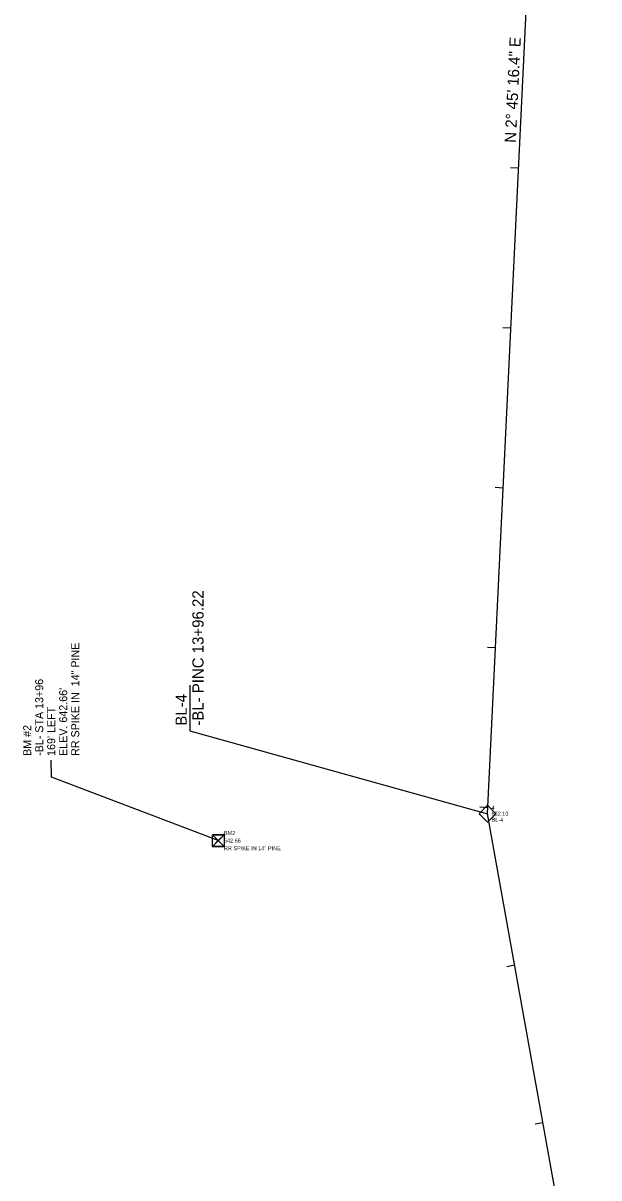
# Model space of a CAD drawing. Extents: x 1373003 to 1373999, y 549956 to 552815.
# Drawn here: x 1373404 to 1373764, y 551431 to 552153 of the extents above; entities that cross this region are included whole.
import ezdxf

# ---------------------------------------------------------------- set-up
doc = ezdxf.new("R2010")
doc.units = 0
for name, color, linetype in [('CTL Bench Mark CELL', 7, 'Continuous'), ('CTL Bench Mark Cogo Comment', 7, 'Continuous'), ('CTL Bench Mark Cogo Elevation', 7, 'Continuous'), ('CTL Bench Mark Cogo Number', 7, 'Continuous'), ('CTL Bench Mark Leader', 7, 'Continuous'), ('CTL Bench Mark Text', 7, 'Continuous'), ('CTL GPS Vertical CELL', 7, 'Continuous'), ('CTL Supplemental Horizontal and Vertical CELL', 7, 'Continuous'), ('CTL Supplemental Horizontal and Vertical Cogo Comment', 7, 'Continuous'), ('CTL Supplemental Horizontal and Vertical Cogo Elevation', 7, 'Continuous'), ('CTL Supplemental Horizontal and Vertical Cogo Number', 7, 'Continuous'), ('Exist Horizontal Baseline Alignment', 7, 'Continuous'), ('Exist Horizontal Baseline Alignment Direction Label', 7, 'Continuous'), ('Exist Horizontal Baseline Alignment Station Label', 7, 'Continuous'), ('Exist Horizontal Baseline Alignment Tick small', 7, 'Continuous')]:
    doc.layers.add(name, color=color, linetype=linetype)

msp = doc.modelspace()

# ---------------------------------------------------------------- linework, layer by layer
at = {"layer": 'CTL Bench Mark CELL'}
msp.add_line((1373526.28, 551641.82), (1373526.28, 551641.82), dxfattribs=at)
msp.add_lwpolyline([(1373522.68, 551645.41), (1373529.86, 551645.41), (1373529.86, 551638.22), (1373522.68, 551638.22)], close=True, dxfattribs=at)
for points in [[(1373529.86, 551645.41), (1373522.68, 551638.22), (1373526.27, 551641.81), (1373529.86, 551638.22), (1373522.68, 551645.41)], [(1373526.27, 551641.81), (1373529.86, 551645.41), (1373522.68, 551645.41), (1373526.27, 551641.81)], [(1373526.27, 551641.81), (1373522.68, 551638.22), (1373529.86, 551638.22), (1373526.27, 551641.81)]]:
    msp.add_lwpolyline(points, dxfattribs=at)
at = {"layer": 'CTL Bench Mark Leader'}
msp.add_lwpolyline([(1373526.28, 551641.82), (1373421.92, 551681.51), (1373421.87, 551692.16)], dxfattribs=at)
at = {"layer": 'CTL GPS Vertical CELL'}
msp.add_lwpolyline([(1373508.45, 551738.97), (1373508.5, 551710.31), (1373694.6, 551658.6)], dxfattribs=at)
at = {"layer": 'CTL Supplemental Horizontal and Vertical CELL'}
msp.add_line((1373694.6, 551658.6), (1373694.6, 551658.6), dxfattribs=at)
msp.add_lwpolyline([(1373689.39, 551658.62), (1373694.63, 551663.86), (1373699.88, 551658.61), (1373694.64, 551653.37)], close=True, dxfattribs=at)
at = {"layer": 'Exist Horizontal Baseline Alignment'}
for p, q in [((1373694.6, 551658.6), (1373724.98, 552290.01)), ((1373764.24, 551270.58), (1373694.6, 551658.6))]:
    msp.add_line(p, q, dxfattribs=at)
at = {"layer": 'Exist Horizontal Baseline Alignment Tick small'}
for p, q in [((1373714, 552061.91), (1373709.01, 552062.15)), ((1373709.2, 551962.03), (1373704.2, 551962.27)), ((1373704.39, 551862.14), (1373699.4, 551862.38)), ((1373699.59, 551762.26), (1373694.59, 551762.5)), ((1373694.78, 551662.37), (1373689.79, 551662.62)), ((1373711.6, 551563.89), (1373706.68, 551563.01)), ((1373729.26, 551465.46), (1373724.34, 551464.58))]:
    msp.add_line(p, q, dxfattribs=at)

# ---------------------------------------------------------------- texts
at = {"layer": 'CTL Bench Mark Cogo Comment'}
msp.add_text('RR SPIKE IN 14" PINE', height=2.5, dxfattribs=at).set_placement((1373529.78, 551635.82))
at = {"layer": 'CTL Bench Mark Cogo Elevation'}
msp.add_text('642.66', height=2.5, dxfattribs=at).set_placement((1373529.78, 551640.57))
at = {"layer": 'CTL Bench Mark Cogo Number'}
msp.add_text('BM2', height=2.5, dxfattribs=at).set_placement((1373529.78, 551645.32))
at = {"layer": 'CTL Bench Mark Text'}
for s, p in [('RR SPIKE IN  14" PINE', (1373439.33, 551694.74)), ('-BL- STA 13+96', (1373416.83, 551694.74)), ("ELEV. 642.66'", (1373431.83, 551694.74)), ("169' LEFT", (1373424.33, 551694.74)), ('BM #2', (1373409.33, 551694.74))]:
    msp.add_text(s, height=5, rotation=90.00002, dxfattribs=at).set_placement(p)
at = {"layer": 'CTL GPS Vertical CELL'}
msp.add_text('BL-4', height=7, rotation=90, dxfattribs=at).set_placement((1373506.58, 551713.62))
at = {"layer": 'CTL Supplemental Horizontal and Vertical Cogo Comment'}
msp.add_text('BL-4', height=2.5, dxfattribs=at).set_placement((1373697.1, 551653.6))
at = {"layer": 'CTL Supplemental Horizontal and Vertical Cogo Elevation'}
msp.add_text('652.10', height=2.5, dxfattribs=at).set_placement((1373697.1, 551657.35))
at = {"layer": 'CTL Supplemental Horizontal and Vertical Cogo Number'}
msp.add_text('4', height=2.5, dxfattribs=at).set_placement((1373697.1, 551661.1))
at = {"layer": 'Exist Horizontal Baseline Alignment Direction Label'}
msp.add_text('N 2%%d 45\' 16.4" E', height=7, rotation=87.24545, dxfattribs=at).set_placement((1373712.27, 552077.72))
at = {"layer": 'Exist Horizontal Baseline Alignment Station Label'}
for s, p in [('-BL- PINC 13+96.22 ', (1373517.08, 551713.62)), ('BL-4', (1373506.58, 551713.62))]:
    msp.add_text(s, height=7, rotation=90, dxfattribs=at).set_placement(p)

doc.saveas('drawing.dxf')
